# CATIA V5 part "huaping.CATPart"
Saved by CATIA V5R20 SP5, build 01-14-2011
Part number: 花瓶
Material "Water": density 1000 kg/m3
Material "Emerald": density 2770 kg/m3, Young's modulus 6e+10 Pa, Poisson ratio 0.27, thermal expansion 7e-06 1/K
Material "Bottle Green": density 7860 kg/m3, Young's modulus 2e+11 Pa, Poisson ratio 0.266
Material "Light Green": density 7860 kg/m3, Young's modulus 2e+11 Pa, Poisson ratio 0.266
Bounding box of the stored display mesh (mm): x -34.978 to 34.978, y -34.978 to 34.943, z -40 to 91.365
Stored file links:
  E:\画图\huaping.CATPart
  C:\Program Files\Dassault Systemes\B20\intel_a\startup\materials\Catalog.CATMaterial
  C:\Program Files\Dassault Systemes\B20\intel_a\startup\materials\eroded_metal_1.jpg
  C:\Program Files\Dassault Systemes\B20\intel_a\startup\materials\fence_3.jpg
  C:\Program Files\Dassault Systemes\B20\intel_a\startup\materials\fence_2.jpg
  C:\Program Files\Dassault Systemes\B20\intel_a\startup\materials\marble_tile.jpg
  C:\Program Files\Dassault Systemes\B20\intel_a\startup\materials\alabaster.jpg
  C:\Program Files\Dassault Systemes\B20\intel_a\startup\materials\blue_env_512x512.jpg
  C:\Program Files\Dassault Systemes\B20\intel_a\startup\materials\brushed_metal2.jpg
  C:\Program Files\Dassault Systemes\B20\intel_a\startup\materials\elm.jpg
  C:\Program Files\Dassault Systemes\B20\intel_a\startup\materials\green_env_512x512.jpg
  C:\Program Files\Dassault Systemes\B20\intel_a\startup\materials\green_leather.jpg
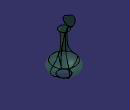
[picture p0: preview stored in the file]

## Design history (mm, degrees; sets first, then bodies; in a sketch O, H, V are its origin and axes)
Body1 (main body), material "Emerald"
  Plane1: type Offset, RefPlane xy-plane, Offset 20
  Plane2: type Offset, RefPlane Plane1, Offset 20
  Plane3: type Offset, RefPlane xy-plane, Offset 20, reversed
  Plane4: type Offset, RefPlane Plane3, Offset 20, reversed
  Plane5: type Offset, RefPlane Plane2, Offset 20
  Sketch1 on Plane4, origin (0, 0, -40), H (1, 0, 0), V (0, 1, 0)
    circle A1 centre (0, 0) radius 15
    radius A1 = 15
  Sketch2 on Plane3, origin (0, 0, -20), H (1, 0, 0), V (0, 1, 0)
    circle A1 centre (0, 0) radius 35
    radius A1 = 35
  Sketch3 on xy-plane, origin (0, 0, 0), H (1, 0, 0), V (0, 1, 0)
    circle A1 centre (0, 0) radius 20
    radius A1 = 20
  Sketch4 on Plane1, origin (0, 0, 20), H (1, 0, 0), V (0, 1, 0)
    circle A1 centre (0, 0) radius 10
    radius A1 = 10
  Sketch5 on Plane2, origin (0, 0, 40), H (1, 0, 0), V (0, 1, 0)
    circle A1 centre (0, 0) radius 8
    radius A1 = 8
  Sketch6 on Plane5, origin (0, 0, 60), H (1, 0, 0), V (0, 1, 0)
    circle A1 centre (0, 0) radius 12
    radius A1 = 12
  Loft1: solid, Sections (Sketch1; Sketch2; Sketch3; Sketch4; Sketch5; Sketch6)
Body2, material "Water"
  Sketch7 on yz-plane, origin (0, 0, 0), H (0, 1, 0), V (0, 0, 1)
    axis line L1 (0, -9.7346) -> (0, -39.962)
    point P1 (0, -9.7346)
    line L2 (0, -9.7346) -> (28.4004, -9.7346)
    point P3 (28.4004, -9.7346)
    line L3 (0, -39.962) -> (14.3148, -39.962)
    point P4 (14.3148, -39.962)
    spline S1 through (14.3148, -39.962) (20.9995, -36.7489) (30.3104, -29.4895) (34.6077, -22.7062) (34.0108, -16.5179) (28.4004, -9.7346)
    point P5 (14.3148, -39.962)
    point P6 (28.4004, -9.7346)
    coincidence: P1 V, P5 P4, P6 P3
    vertical: L1 V
    horizontal: L2 H, L3 H
  Shaft1: profile Sketch7, axis Sketch7.L1, angle 360
Body3, material "Light Green"
  Sketch8 on yz-plane, origin (0, 0, 0), H (0, 1, 0), V (0, 0, 1)
    spline S1 through (-7.3879, -26.9913) (-5.7102, 11.9562) (16.819, 82.9219)
  Plane6: type Normal, Curve Sketch8, RefPoint vertex of Sketch8
  Sketch9 on Plane6, origin (0, 37.1516, 72.5032), H (1, 0, 0), V (0, -0.89, 0.456)
    circle A1 centre (0, 22.9173) radius 0.4
    point P1 (0, 22.9173)
    radius A1 = 0.4
    coincidence: P1 V
  Rib1: profile Sketch9, centre curve Sketch8
Body4, material "Bottle Green"
  Sketch10 on Plane6, origin (0, 37.1516, 72.5032), H (1, 0, 0), V (0, -0.89, 0.456)
    spline S1 through (-5.1954, 35.7411) (5.4404, 38.4068) (6.5327, 14.5781) (-13.7782, 29.7961) (-5.1954, 35.7411)
    point P1 (-5.1954, 35.7411)
    point P2 (-5.1954, 35.7411)
    coincidence: P1 P2
  Pad1: profile Sketch10, direction (0, 0.456, 0.89), length 1
  Sketch11 on yz-plane, origin (0, 0, 0), H (0, 1, 0), V (0, 0, 1)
